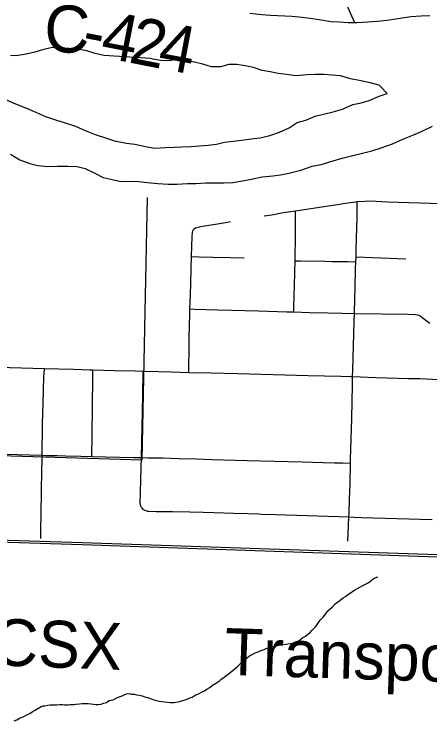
# Model space of a CAD drawing. Extents: x 0 to 34, y 0 to 22.
# Drawn here: x 28.877 to 29.379, y 17.958 to 18.812 of the extents above; entities that cross this region are included whole.
import ezdxf

# ---------------------------------------------------------------- set-up
doc = ezdxf.new("R2010")
doc.units = 0
for name, color, linetype in [('GM_X_City_Street', 7, 'Continuous'), ('GM_X_County_Road_Text', 7, 'Continuous'), ('GM_X_Major_River', 7, 'Continuous'), ('GM_X_Minor_River', 7, 'Continuous'), ('GM_X_Rail_Line', 7, 'Continuous'), ('GM_X_Rail_Line_Text', 7, 'Continuous'), ('GM_X_State_Route', 7, 'Continuous'), ('GM_X_Township_Road', 7, 'Continuous')]:
    doc.layers.add(name, color=color, linetype=linetype)

msp = doc.modelspace()

# ---------------------------------------------------------------- linework, layer by layer
at = {"layer": 'GM_X_City_Street'}
msp.add_line((29.21568, 18.47171), (29.21591, 18.48316), dxfattribs=at)
for points in [[(29.17918, 18.56794), (29.18836, 18.56932), (29.20243, 18.57188), (29.21715, 18.57402), (29.21965, 18.57439), (29.26511, 18.58143), (29.28049, 18.58381), (29.28993, 18.58494), (29.29177, 18.58516), (29.30091, 18.58583), (29.30755, 18.58608), (29.32839, 18.58509), (29.39297, 18.58282), (29.4549, 18.58112), (29.50525, 18.57943), (29.54154, 18.57862), (29.57696, 18.57756), (29.59732, 18.57677)], [(29.28925, 18.48089), (29.28976, 18.50372), (29.2901, 18.51256), (29.29032, 18.51849), (29.29061, 18.52607), (29.29095, 18.54098), (29.29172, 18.56581), (29.29179, 18.57884), (29.29178, 18.58069), (29.29177, 18.58516)], [(29.21591, 18.48316), (29.2165, 18.49997), (29.21686, 18.51377), (29.21674, 18.5224), (29.21698, 18.53702), (29.21699, 18.55623), (29.21715, 18.57402)], [(29.09378, 18.55167), (29.09469, 18.55247), (29.09631, 18.55338), (29.09819, 18.55408), (29.10132, 18.55491), (29.10495, 18.55554), (29.12305, 18.55847), (29.13485, 18.56044), (29.13865, 18.56107)], [(29.09152, 18.51885), (29.09175, 18.53099), (29.09245, 18.543), (29.09287, 18.54796), (29.09316, 18.54971), (29.09378, 18.55167)], [(29.09075, 18.48661), (29.0912, 18.50433), (29.09152, 18.51885)], [(29.09152, 18.51885), (29.10069, 18.51851), (29.11738, 18.51823), (29.13848, 18.51773), (29.15514, 18.51745)], [(29.21686, 18.51377), (29.22309, 18.51365), (29.25289, 18.5131), (29.26157, 18.5129), (29.28083, 18.51273), (29.2901, 18.51256)], [(29.29032, 18.51849), (29.30998, 18.51773), (29.35056, 18.51607)], [(29.0896, 18.45563), (29.09021, 18.47213), (29.09075, 18.48661)], [(29.2151, 18.45185), (29.21532, 18.45867), (29.21568, 18.47005), (29.21568, 18.47171)], [(29.08817, 18.37892), (29.08834, 18.3903), (29.08851, 18.40142), (29.08884, 18.42007), (29.0895, 18.44967), (29.0896, 18.45563)], [(29.0896, 18.45563), (29.09542, 18.45544), (29.12338, 18.45451), (29.1725, 18.45307), (29.2067, 18.45207), (29.2151, 18.45185)], [(29.2151, 18.45185), (29.23423, 18.45136), (29.2562, 18.4508), (29.27378, 18.45036), (29.28844, 18.44998)], [(29.28844, 18.44998), (29.35327, 18.44914), (29.36205, 18.44885), (29.364, 18.44862), (29.36596, 18.44807), (29.36778, 18.44717), (29.36991, 18.44563), (29.37943, 18.4382)], [(28.97115, 18.27739), (28.97162, 18.30377), (28.97199, 18.33727), (28.97239, 18.37259), (28.9725, 18.38206)], [(29.03113, 18.27595), (29.03189, 18.31271), (29.03258, 18.35122), (29.03293, 18.38048)], [(29.03116, 18.21558), (29.03073, 18.21627), (29.03035, 18.21704), (29.03014, 18.21776), (29.02996, 18.2185), (29.02978, 18.2194), (29.02969, 18.22047), (29.02966, 18.22149), (29.02998, 18.23275), (29.03048, 18.25073), (29.03113, 18.27595)]]:
    msp.add_lwpolyline(points, dxfattribs=at)
at = {"layer": 'GM_X_Major_River'}
for points in [[(29.3795, 18.80973), (29.36887, 18.80925), (29.35634, 18.80843), (29.33844, 18.80548), (29.32778, 18.80386), (29.316, 18.80265), (29.3046, 18.8018), (29.2917, 18.80138), (29.2807, 18.80128), (29.26972, 18.80195), (29.25988, 18.80258), (29.24592, 18.80484), (29.23496, 18.80627), (29.22514, 18.80766), (29.21266, 18.80875), (29.18692, 18.81018), (29.17632, 18.81083), (29.16195, 18.81234)], [(28.98543, 18.76186), (28.97526, 18.76402), (28.96511, 18.76732), (28.95417, 18.7695), (28.94357, 18.77016), (28.93374, 18.77079), (28.92314, 18.77145), (28.91169, 18.76871), (28.90213, 18.76592), (28.89182, 18.76314), (28.88231, 18.76187), (28.87282, 18.76136)], [(28.86685, 18.70873), (28.87885, 18.70348), (28.89235, 18.6982), (28.90434, 18.69295), (28.91521, 18.68811), (28.92723, 18.684), (28.93888, 18.68028), (28.95128, 18.67616), (28.9629, 18.67131), (28.97528, 18.66643), (28.98881, 18.6619), (28.99858, 18.65861), (29.01292, 18.65596), (29.02311, 18.65456), (29.03593, 18.65195), (29.04725, 18.64975), (29.06016, 18.65056), (29.07041, 18.65105), (29.07989, 18.65119), (29.0909, 18.65166), (29.10116, 18.65253), (29.1118, 18.6534), (29.12169, 18.65466), (29.13123, 18.65707), (29.14188, 18.65831), (29.15177, 18.65957), (29.16357, 18.66116), (29.1746, 18.6624), (29.18604, 18.66514), (29.1979, 18.66901), (29.20942, 18.67441), (29.21907, 18.68061), (29.22977, 18.68375), (29.24089, 18.6884), (29.26264, 18.69353), (29.2741, 18.69703), (29.28638, 18.70241), (29.29629, 18.70443), (29.30622, 18.70721), (29.31812, 18.71259), (29.32806, 18.71576), (29.3181, 18.72589), (29.30718, 18.72883), (29.29587, 18.73102), (29.28343, 18.73362), (29.27139, 18.73697), (29.26156, 18.73799), (29.25134, 18.73863), (29.24111, 18.7389), (29.23124, 18.73839), (29.21756, 18.73723), (29.20622, 18.73866), (29.1964, 18.74006), (29.18659, 18.74183), (29.17678, 18.74361), (29.16627, 18.7473), (29.15646, 18.74907), (29.14627, 18.75085), (29.13679, 18.75072), (29.12647, 18.74795), (29.11549, 18.74823), (29.10533, 18.75116), (29.09516, 18.7537), (29.07478, 18.75726), (29.06487, 18.75524), (29.05464, 18.75551), (29.04483, 18.75728), (29.04258, 18.7581)], [(29.04258, 18.7581), (28.98543, 18.76186)], [(28.87303, 18.6425), (28.88423, 18.63575), (28.89624, 18.63126), (28.90603, 18.62873), (28.91813, 18.62766), (28.92952, 18.62812), (28.94203, 18.62818), (28.95338, 18.6275), (28.96318, 18.62535), (28.97479, 18.61973), (28.98488, 18.61453), (28.99581, 18.61197), (29.00598, 18.60943), (29.01585, 18.60994), (29.02759, 18.60963), (29.03855, 18.60821), (29.05065, 18.60713), (29.06314, 18.60643), (29.07375, 18.60616), (29.08666, 18.60696), (29.09728, 18.60706), (29.10868, 18.60791), (29.12043, 18.60798), (29.13104, 18.60771), (29.14129, 18.6082), (29.1531, 18.61017), (29.16568, 18.61288), (29.17674, 18.61526), (29.18966, 18.61644), (29.19918, 18.61771), (29.20909, 18.61973), (29.22359, 18.62315), (29.23737, 18.62811), (29.24804, 18.63012), (29.26257, 18.63467), (29.27365, 18.63781), (29.28471, 18.64055), (29.29807, 18.64363), (29.30953, 18.64674), (29.32061, 18.65025), (29.3344, 18.65521), (29.34668, 18.66059), (29.35894, 18.66559), (29.37006, 18.67023), (29.38274, 18.67636)]]:
    msp.add_lwpolyline(points, dxfattribs=at)
at = {"layer": 'GM_X_Minor_River'}
for points in [[(29.28887, 18.80135), (29.27661, 18.82805)], [(29.05262, 17.98173), (29.05564, 17.98127), (29.05905, 17.98079), (29.06245, 17.98031), (29.06625, 17.9802), (29.07004, 17.98009), (29.07271, 17.98039), (29.07539, 17.98108), (29.07845, 17.98175), (29.08113, 17.98243), (29.08382, 17.98349), (29.08726, 17.98454), (29.08957, 17.98561), (29.09226, 17.98667), (29.09458, 17.98813), (29.09689, 17.9892), (29.09921, 17.99027), (29.10152, 17.99135), (29.10422, 17.99279), (29.1073, 17.99422), (29.11001, 17.99605), (29.11349, 17.99823), (29.117, 18.00117), (29.12163, 18.0037), (29.12473, 18.00589), (29.12745, 18.00809), (29.13055, 18.01028), (29.13288, 18.01211), (29.13561, 18.01432), (29.13833, 18.01652), (29.14143, 18.01871), (29.14417, 18.0213), (29.14728, 18.02387), (29.15001, 18.02645), (29.15353, 18.02977), (29.15588, 18.03236), (29.15859, 18.03419), (29.1617, 18.03638), (29.16479, 18.03819), (29.16749, 18.03963), (29.16979, 18.04033), (29.1721, 18.0414), (29.17441, 18.04247), (29.17671, 18.04317), (29.1794, 18.04423), (29.18248, 18.04566), (29.18631, 18.04669), (29.18937, 18.04775), (29.19319, 18.04839), (29.19702, 18.04942), (29.2077, 18.05102), (29.21113, 18.0513), (29.21342, 18.05161), (29.21571, 18.05193), (29.21878, 18.05336), (29.22072, 18.05444), (29.22305, 18.05628), (29.22615, 18.05847), (29.22924, 18.06028), (29.23196, 18.06248), (29.23469, 18.06469), (29.23703, 18.0669), (29.23939, 18.06949), (29.24174, 18.07209), (29.24412, 18.07544), (29.24689, 18.07954), (29.25042, 18.08324), (29.25357, 18.08695), (29.25633, 18.09067), (29.25868, 18.09289), (29.2618, 18.09584), (29.26494, 18.09917), (29.26727, 18.101), (29.2692, 18.10209), (29.27114, 18.10355), (29.27464, 18.10649), (29.27774, 18.10831), (29.28007, 18.11014), (29.28317, 18.11233), (29.28743, 18.11525), (29.2913, 18.11742), (29.29477, 18.11922), (29.29786, 18.12103), (29.30094, 18.12246), (29.30403, 18.12427), (29.30635, 18.12573), (29.31062, 18.12903), (29.31257, 18.13049), (29.31525, 18.13156), (29.31602, 18.13153), (29.31564, 18.13192)], [(28.8772, 17.9579), (28.88066, 17.95932), (28.88375, 17.96113), (28.88682, 17.96218), (28.8899, 17.96362), (28.89337, 17.96541), (28.89607, 17.96686), (28.89916, 17.96867), (28.90188, 17.97049), (28.90999, 17.9752), (28.91229, 17.9759), (28.9142, 17.97622), (28.91801, 17.97687), (28.92068, 17.97717), (28.92525, 17.97742), (28.92866, 17.97732), (28.93247, 17.9776), (28.9355, 17.97751), (28.93816, 17.97743), (28.94082, 17.97735), (28.94272, 17.9773), (28.945, 17.97762), (28.9469, 17.97756), (28.94919, 17.97787), (28.95186, 17.97818), (28.95604, 17.97844), (28.95947, 17.97872), (28.9629, 17.979), (28.96669, 17.97889), (28.9701, 17.97841), (28.97312, 17.97795), (28.97616, 17.97786), (28.97881, 17.97778), (28.98224, 17.97806), (28.98531, 17.97911), (28.98876, 17.98015), (28.99224, 17.98234), (28.99683, 17.98334), (28.99953, 17.98479), (29.00223, 17.98623), (29.0053, 17.98728), (29.0076, 17.98798), (29.0103, 17.98942), (29.01299, 17.99048), (29.01603, 17.99077), (29.01906, 17.99031), (29.0221, 17.99022), (29.02511, 17.98937), (29.02851, 17.98889), (29.03191, 17.98804), (29.03529, 17.9868), (29.03868, 17.98594), (29.0417, 17.98509), (29.04396, 17.98427), (29.04583, 17.98345), (29.05262, 17.98173)]]:
    msp.add_lwpolyline(points, dxfattribs=at)
at = {"layer": 'GM_X_Rail_Line'}
for points in [[(27.58592, 18.7118), (27.76572, 18.62271), (27.67886, 18.44017), (27.80362, 18.3801), (27.8211, 18.41218), (27.92663, 18.35794), (27.96744, 18.34103), (28.04847, 18.31828), (28.26949, 18.29939), (28.30091, 18.29671), (28.35687, 18.29379), (28.62272, 18.28575), (29.03198, 18.27338), (29.03839, 18.59005)], [(26.76773, 18.04678), (26.84363, 18.05726), (26.91386, 18.07056), (26.94891, 18.08015), (27.06818, 18.10637), (27.15455, 18.12707), (27.2346, 18.14439), (27.34883, 18.17031), (27.41069, 18.1844), (27.46882, 18.19648), (27.53407, 18.20707), (27.59754, 18.21236), (27.64543, 18.21488), (27.85515, 18.20909), (28.1266, 18.20004), (28.52723, 18.18722), (28.95953, 18.1734), (29.40063, 18.15831)], [(26.76804, 18.04432), (26.84404, 18.05481), (26.91442, 18.06813), (26.94951, 18.07774), (27.06874, 18.10395), (27.1551, 18.12465), (27.23513, 18.14196), (27.34939, 18.16789), (27.41122, 18.18197), (27.46927, 18.19404), (27.53437, 18.2046), (27.59771, 18.20988), (27.64546, 18.21239), (27.85508, 18.20661), (28.12652, 18.19756), (28.52715, 18.18474), (28.95945, 18.17091), (29.40055, 18.15582)]]:
    msp.add_lwpolyline(points, dxfattribs=at)
at = {"layer": 'GM_X_State_Route'}
for points in [[(28.85316, 18.38565), (28.85844, 18.38544), (28.87199, 18.3849), (28.91383, 18.38366), (28.94897, 18.38261), (28.96888, 18.38217), (28.9725, 18.38206), (28.99809, 18.3813), (29.02362, 18.38076), (29.03293, 18.38048), (29.03594, 18.38039)], [(29.03594, 18.38039), (29.06705, 18.37945), (29.08817, 18.37892), (29.115, 18.37825), (29.14731, 18.37735), (29.23256, 18.37506), (29.27174, 18.37416), (29.28356, 18.37392), (29.28615, 18.37387), (29.31443, 18.37275), (29.35278, 18.37171), (29.36719, 18.37131), (29.38253, 18.3709), (29.40885, 18.37018), (29.42674, 18.36969), (29.44984, 18.36905), (29.46789, 18.36848), (29.49857, 18.36773), (29.51869, 18.36707), (29.52119, 18.36701), (29.53438, 18.36677)]]:
    msp.add_lwpolyline(points, dxfattribs=at)
at = {"layer": 'GM_X_Township_Road'}
for p, q in [((28.91096, 18.27192), (28.91117, 18.27878)), ((29.28365, 18.26931), (29.28378, 18.27456)), ((29.28165, 18.20426), (29.28183, 18.20938)), ((29.28165, 18.20426), (29.28775, 18.20406)), ((29.36821, 18.20151), (29.38229, 18.20107))]:
    msp.add_line(p, q, dxfattribs=at)
for points in [[(29.28844, 18.44998), (29.28894, 18.46886), (29.28925, 18.48089)], [(29.28615, 18.37387), (29.28638, 18.38173), (29.28811, 18.44085), (29.28844, 18.44998)], [(28.91117, 18.27878), (28.91127, 18.28959), (28.9113, 18.2934), (28.91136, 18.30093), (28.91154, 18.31584), (28.91228, 18.34192), (28.9126, 18.3562), (28.91331, 18.37484), (28.91342, 18.3767), (28.91383, 18.38366)], [(29.28378, 18.27456), (29.28408, 18.28607), (29.28512, 18.32336), (29.28548, 18.34388), (29.2859, 18.36302), (29.28615, 18.37387)], [(28.85103, 18.28057), (28.91117, 18.27878), (28.91517, 18.27868)], [(28.90937, 18.17802), (28.90941, 18.18883), (28.90988, 18.20826), (28.91024, 18.2346), (28.91062, 18.26112), (28.91096, 18.27192)], [(28.91517, 18.27868), (28.92915, 18.27833), (28.93915, 18.27811)], [(28.93915, 18.27811), (28.95785, 18.2777), (28.97115, 18.27739)], [(28.97115, 18.27739), (28.98757, 18.27706), (29.02137, 18.27622), (29.03113, 18.27595)], [(29.03113, 18.27595), (29.03876, 18.27574), (29.05702, 18.2755), (29.07566, 18.27493), (29.09742, 18.27431), (29.11605, 18.27366), (29.15831, 18.27261), (29.19185, 18.2718), (29.22505, 18.27094), (29.25075, 18.27015), (29.26414, 18.26979), (29.27452, 18.2695), (29.28365, 18.26931)], [(29.28183, 18.20938), (29.28239, 18.22577), (29.28302, 18.24442), (29.28365, 18.26931)], [(29.03116, 18.21558), (29.03205, 18.21445), (29.03303, 18.21358), (29.03399, 18.21302), (29.03506, 18.21239), (29.03617, 18.21195), (29.03736, 18.21159), (29.03826, 18.21138), (29.03995, 18.21123), (29.04921, 18.21103), (29.06742, 18.21079)], [(29.06742, 18.21079), (29.06838, 18.21077), (29.08955, 18.21034)], [(29.08955, 18.21034), (29.10569, 18.21002), (29.11858, 18.2096)], [(29.11858, 18.2096), (29.14237, 18.20882), (29.16014, 18.20822), (29.17275, 18.20784), (29.17666, 18.20772)], [(29.17666, 18.20772), (29.19328, 18.20721), (29.28165, 18.20426)], [(29.28055, 18.17481), (29.28126, 18.19408), (29.28165, 18.20426)], [(29.28775, 18.20406), (29.29682, 18.20376), (29.36821, 18.20151)]]:
    msp.add_lwpolyline(points, dxfattribs=at)

# ---------------------------------------------------------------- texts
at = {"layer": 'GM_X_County_Road_Text'}
for s, rotation, p in [('C', 357.4701, (28.91261, 18.76657)), ('4', 348.84009, (28.97991, 18.76037)), ('2', 348.82938, (29.01424, 18.7536)), ('4', 349.37792, (29.04916, 18.7467)), ('-', 349.11565, (28.95706, 18.76476))]:
    msp.add_text(s, height=0.05682, rotation=rotation, dxfattribs=at).set_placement(p)
at = {"layer": 'GM_X_Rail_Line_Text'}
for s, height, rotation, p in [('CSX', 0.056629, 357.88901, (28.85077, 18.02514)), ('Transportation,', 0.0566288, 358.17915, (29.13076, 18.01352))]:
    msp.add_text(s, height=height, rotation=rotation, dxfattribs=at).set_placement(p)

doc.saveas('drawing.dxf')
